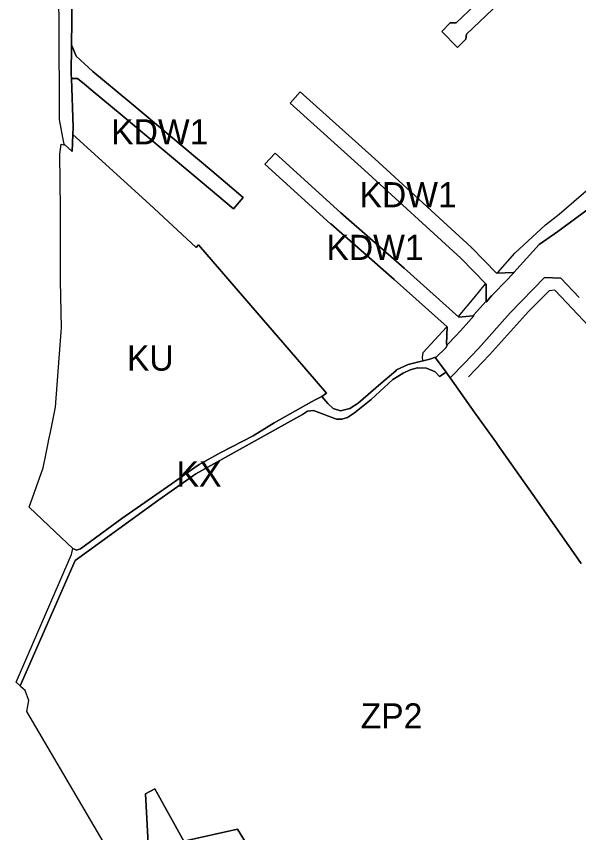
# Model space of a CAD drawing. Extents: x -284239 to -281592, y 34477 to 37267.
# Drawn here: x -284182.4 to -283958.8, y 34964.3 to 35288.9 of the extents above; entities that cross this region are included whole.
import ezdxf

# ---------------------------------------------------------------- set-up
doc = ezdxf.new("R2010")
doc.units = 0
for name, color, linetype in [('linie_rozgraniczajace', 7, 'Continuous'), ('linie_zabudowy_nieprzekraczalne', 7, 'Continuous'), ('oznaczenia_przeznaczen', 7, 'Continuous')]:
    doc.layers.add(name, color=color, linetype=linetype)

msp = doc.modelspace()

# ---------------------------------------------------------------- linework, layer by layer
at = {"layer": 'linie_rozgraniczajace'}
for points in [[(-284159.831, 35325.216), (-284160.415, 35277.536), (-284160.561, 35265.687), (-284160.506, 35264.137), (-284159.822, 35244.857), (-284159.921, 35241.818), (-284160.137, 35235.169), (-284163.417, 35238.047), (-284163.88, 35240.73), (-284165.22, 35247.87), (-284165.33, 35286.95), (-284166.41, 35344.78)], [(-284160.506, 35264.137), (-284158.008, 35264.137), (-284155.26, 35261.875), (-284151.938, 35259.139), (-284151.809, 35259.032), (-284141.058, 35250.159), (-284108.466, 35222.855), (-284096.039, 35212.279), (-284092.151, 35216.849), (-284104.593, 35227.438), (-284137.221, 35254.771), (-284152.022, 35266.988), (-284152.072, 35267.114), (-284155.232, 35270.018), (-284158.555, 35273.071), (-284160.415, 35277.536), (-284159.831, 35325.216)], [(-283989.883, 35303.101), (-284007.478, 35286.3), (-284009.859, 35286.3), (-284013.167, 35282.86), (-284006.949, 35276.51), (-284003.641, 35279.817), (-284003.377, 35281.802), (-283985.121, 35299.264)], [(-283985.121, 35299.264), (-284003.377, 35281.802), (-284003.641, 35279.817), (-284006.949, 35276.51), (-284013.167, 35282.86), (-284009.859, 35286.3), (-284007.478, 35286.3), (-283989.883, 35303.101)], [(-284053.403, 35210.784), (-284079.51, 35234.511), (-284083.545, 35230.071), (-284057.417, 35206.325), (-284057.382, 35206.297), (-284032.119, 35184.205), (-284011.053, 35165.369), (-284011.309, 35158.601), (-284011.045, 35158.258), (-284011.418, 35157.246), (-284015.641, 35153.14), (-284015.75, 35153.29), (-284017.94, 35152.55), (-284024.486, 35150.955), (-284026.56, 35150.45), (-284031.15, 35148.27), (-284031.53, 35147.95), (-284037.43, 35142.92), (-284046.4, 35134.99), (-284049.76, 35132.87), (-284053.46, 35132.03), (-284056.41, 35132.87), (-284058.57, 35134.92), (-284060.95, 35137.76), (-284059.064, 35138.984), (-284071.404, 35153.284), (-284089.132, 35173.889), (-284109.901, 35198.032), (-284110.828, 35196.974), (-284129.481, 35214.138), (-284159.921, 35241.818), (-284159.822, 35244.857), (-284160.506, 35264.137)], [(-283955.019, 35212.204), (-283967.091, 35203.375), (-283974.479, 35198.149), (-283984.588, 35186.995), (-283984.64, 35187.035), (-283991.471, 35186.709), (-284001.414, 35196.947), (-284001.491, 35197), (-284001.54, 35197.07), (-284039.842, 35232.141), (-284069.477, 35258.825), (-284073.492, 35254.366), (-284043.874, 35227.7), (-284005.657, 35192.704), (-283995.58, 35182.328), (-283995.58, 35175.586), (-284000.606, 35170.04), (-284000.825, 35169.835), (-284006.38, 35169.24), (-284028.143, 35188.696), (-284053.403, 35210.784)], [(-283958.538, 35177.051), (-283965.895, 35184.8), (-283972.296, 35185.037), (-283972.411, 35185.062), (-283985.981, 35171.015), (-283998.603, 35156.804), (-284004.338, 35150.819), (-284009.829, 35145.092), (-284010.541, 35146.093), (-284010.614, 35146.195), (-284011.454, 35147.373), (-284015.641, 35153.14), (-284011.418, 35157.246), (-284011.045, 35158.258), (-284007.671, 35161.789), (-284005.896, 35163.646), (-284003.568, 35166.269), (-284000.358, 35169.885), (-284000.825, 35169.835), (-284000.606, 35170.04), (-283995.58, 35175.586), (-283995.58, 35175.266), (-283993.39, 35177.733), (-283993.311, 35177.789), (-283993.247, 35177.888), (-283992.259, 35178.909), (-283988.089, 35183.227), (-283984.508, 35186.933), (-283984.588, 35186.995), (-283974.479, 35198.149), (-283967.091, 35203.375), (-283955.019, 35212.204)], [(-283957.788, 35071.359), (-283962.68, 35078.32), (-283977.05, 35098.77), (-283991.04, 35118.67), (-283991.43, 35119.23), (-284000, 35131.27), (-284009.829, 35145.092), (-284004.338, 35150.819), (-283998.603, 35156.804), (-283985.981, 35171.015), (-283972.411, 35185.062), (-283972.296, 35185.037), (-283965.895, 35184.8), (-283958.538, 35177.051)], [(-284143.01, 34952.37), (-284178.17, 35012.4), (-284177.43, 35016.87), (-284178.83, 35020.78), (-284180.7, 35022.4), (-284180.911, 35022.615), (-284180.875, 35022.707), (-284159.047, 35072.449), (-284125.71, 35096.592), (-284111.025, 35106.911), (-284068.56, 35130.591), (-284066.575, 35131.848), (-284064.194, 35132.112), (-284055.066, 35128.673), (-284052.949, 35128.673), (-284050.7, 35129.334), (-284047.922, 35131.186), (-284041.307, 35136.478), (-284032.708, 35144.482), (-284028.607, 35146.995), (-284025.829, 35148.318), (-284022.919, 35149.112), (-284019.347, 35148.979), (-284015.775, 35147.524), (-284014.055, 35145.672), (-284011.454, 35147.373), (-284010.614, 35146.195), (-284010.541, 35146.093), (-284009.829, 35145.092), (-284000, 35131.27), (-283991.43, 35119.23), (-283991.04, 35118.67), (-283977.05, 35098.77), (-283962.68, 35078.32), (-283957.788, 35071.359)], [(-284061.56, 34912.17), (-284094.42, 34965.69), (-284115.75, 34960.83), (-284127.33, 34981.67), (-284131.02, 34979.72), (-284129.86, 34957.6)], [(-284129.86, 34957.6), (-284131.02, 34979.72), (-284127.33, 34981.67), (-284115.75, 34960.83), (-284094.42, 34965.69), (-284061.56, 34912.17)]]:
    msp.add_lwpolyline(points, dxfattribs=at)
for points in [[(-284160.561, 35265.687), (-284160.415, 35277.536), (-284158.555, 35273.071), (-284155.232, 35270.018), (-284152.072, 35267.114), (-284152.022, 35266.988), (-284137.221, 35254.771), (-284104.593, 35227.438), (-284092.151, 35216.849), (-284096.039, 35212.279), (-284108.466, 35222.855), (-284141.058, 35250.159), (-284151.809, 35259.032), (-284151.938, 35259.139), (-284155.26, 35261.875), (-284158.008, 35264.137), (-284160.506, 35264.137)], [(-284073.492, 35254.366), (-284069.477, 35258.825), (-284039.842, 35232.141), (-284001.54, 35197.07), (-284001.491, 35197), (-284001.414, 35196.947), (-283991.471, 35186.709), (-283984.64, 35187.035), (-283984.588, 35186.995), (-283984.508, 35186.933), (-283988.089, 35183.227), (-283992.259, 35178.909), (-283993.247, 35177.888), (-283993.311, 35177.789), (-283993.39, 35177.733), (-283995.58, 35175.266), (-283995.58, 35175.586), (-283995.58, 35182.328), (-284005.657, 35192.704), (-284043.874, 35227.7)], [(-284177.23, 35093.69), (-284171.73, 35109.33), (-284170.556, 35115.118), (-284169.742, 35119.129), (-284169.437, 35120.635), (-284168.86, 35123.48), (-284166.8, 35133.52), (-284165.36, 35152.95), (-284164.43, 35165.05), (-284164.87, 35183.7), (-284164.87, 35212.22), (-284165.12, 35234.01), (-284164.55, 35238.05), (-284163.534, 35237.768), (-284163.36, 35237.72), (-284163.417, 35238.047), (-284160.137, 35235.169), (-284159.921, 35241.818), (-284129.481, 35214.138), (-284110.828, 35196.974), (-284109.901, 35198.032), (-284089.132, 35173.889), (-284071.404, 35153.284), (-284059.064, 35138.984), (-284060.95, 35137.76), (-284063.59, 35136.33), (-284064.998, 35135.539), (-284079.89, 35127.17), (-284088.26, 35122), (-284101.1, 35115.41), (-284109.72, 35110.62), (-284111.788, 35109.183), (-284120.83, 35102.9), (-284140.39, 35089.18), (-284156.9, 35077.15), (-284158.4, 35076.65), (-284159.9, 35077.25), (-284166.951, 35083.939)], [(-284083.545, 35230.071), (-284079.51, 35234.511), (-284053.403, 35210.784), (-284028.143, 35188.696), (-284006.38, 35169.24), (-284000.825, 35169.835), (-284000.358, 35169.885), (-284003.568, 35166.269), (-284005.896, 35163.646), (-284007.671, 35161.789), (-284011.045, 35158.258), (-284011.309, 35158.601), (-284011.053, 35165.369), (-284032.119, 35184.205), (-284057.382, 35206.297), (-284057.417, 35206.325)], [(-284182.39, 35024.12), (-284160.51, 35074.87), (-284159.9, 35077.25), (-284158.4, 35076.65), (-284156.9, 35077.15), (-284140.39, 35089.18), (-284120.83, 35102.9), (-284111.788, 35109.183), (-284109.72, 35110.62), (-284101.1, 35115.41), (-284088.26, 35122), (-284079.89, 35127.17), (-284064.998, 35135.539), (-284063.59, 35136.33), (-284060.95, 35137.76), (-284058.57, 35134.92), (-284056.41, 35132.87), (-284053.46, 35132.03), (-284049.76, 35132.87), (-284046.4, 35134.99), (-284037.43, 35142.92), (-284031.53, 35147.95), (-284031.15, 35148.27), (-284026.56, 35150.45), (-284024.486, 35150.955), (-284017.94, 35152.55), (-284015.75, 35153.29), (-284015.641, 35153.14), (-284011.454, 35147.373), (-284014.055, 35145.672), (-284015.775, 35147.524), (-284019.347, 35148.979), (-284022.919, 35149.112), (-284025.829, 35148.318), (-284028.607, 35146.995), (-284032.708, 35144.482), (-284041.307, 35136.478), (-284047.922, 35131.186), (-284050.7, 35129.334), (-284052.949, 35128.673), (-284055.066, 35128.673), (-284064.194, 35132.112), (-284066.575, 35131.848), (-284068.56, 35130.591), (-284111.025, 35106.911), (-284125.71, 35096.592), (-284159.047, 35072.449), (-284180.875, 35022.707), (-284180.911, 35022.615)]]:
    msp.add_lwpolyline(points, close=True, dxfattribs=at)
at = {"layer": 'linie_zabudowy_nieprzekraczalne'}
for points in [[(-283990.921, 35187.021), (-283984.165, 35194.724), (-283971.994, 35205.969), (-283966.57, 35210.202), (-283950.959, 35223.563), (-283930.454, 35240.828), (-283881.638, 35283.624), (-283935.094, 35339.421)], [(-284006.531, 35169.558), (-284000.314, 35176.967), (-283995.816, 35182.523)], [(-283913.266, 35112.937), (-283934.29, 35141.146), (-283954.663, 35165.487), (-283968.289, 35180.039), (-283970.538, 35179.775), (-283978.741, 35171.44), (-283994.219, 35154.242), (-284002.641, 35145.469)], [(-284020.677, 35152.06), (-284020.809, 35153.383), (-284020.545, 35155.235), (-284011.294, 35165.325)]]:
    msp.add_lwpolyline(points, dxfattribs=at)

# ---------------------------------------------------------------- texts
at = {"layer": 'oznaczenia_przeznaczen'}
for s, p in [('KDW1', (-284144.654, 35237.951)), ('KDW1', (-284045.92, 35212.939)), ('KDW1', (-284059.07, 35191.991)), ('KU', (-284138.392, 35147.986)), ('KX', (-284118.662, 35101.911)), ('ZP2', (-284045.453, 35005.698))]:
    msp.add_text(s, height=10, dxfattribs=at).set_placement(p)

doc.saveas('drawing.dxf')
